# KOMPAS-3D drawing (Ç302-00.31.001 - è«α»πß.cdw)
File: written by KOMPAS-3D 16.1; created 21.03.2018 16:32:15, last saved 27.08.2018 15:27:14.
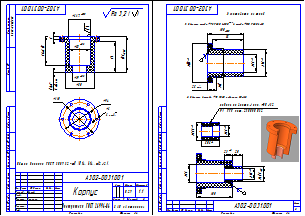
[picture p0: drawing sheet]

Sheets 1-2: A4, portrait

Title block, sheet 1: name: Корпус; designation: А302-00.31.001; material: Полипропилен  ГОСТ 26996-86; mass: 0,29; scale: 1:1; sheet number: 1; sheets: 2; organisation: ЗАО «Астерион»; sheet format: A4; stored path: Z:\Мембранные насосы\Мембранный электропривод\А302-00.00.000 - ASTRA-302 (МЭ200)\Чертежи\А302-00.31.001 - Корпус.cdw; drawn by: Милов; technical control: Лучихин
Title block, sheet 2: sheet number: 2

Views: Вид 1, Местный разрез 1, Вид:1, Проекционный вид 2
Referenced files in Z:\Мембранные насосы\Мембранный электропривод\А302-00.00.000 - ASTRA-302 (МЭ200)\3Д\: А302-00.31.001 - Корпус.m3d
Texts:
  1. Вварить трубу  75 PN20 L=100 +0,5  в трубу  110 PN20 L=30
  min
  редукция внутр./нар.  50/32
  FV PPR арт. 210050032
  2. Вварить в трубу  75 PN20 редукцию 50/32
  Изготовить из труб
  Общие допуски ГОСТ 30893.2-mK (H14, h14,  t2/2).
  Ra 3,2
  Ra 3,2 ( )
Dimensions and other numbers on the sheet: 58; 61,7; 39; 100; 86; 9; 80±0,15; 1; 3 фаски; 1,6; 75; 50; 110; 81; 25; 32; 50,3; 50,6; 41,2; 23; 20; 94; 6; 6 отв.; 1:1; 0,29; 2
